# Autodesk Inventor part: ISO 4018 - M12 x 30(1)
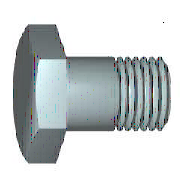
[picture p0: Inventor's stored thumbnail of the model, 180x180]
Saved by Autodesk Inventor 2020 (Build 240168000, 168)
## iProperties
Created: 2019-01
Part Number: ISO 4018 - M12 x 30(1)
Material: Ocel
Description: Šrouby se šestihrannou hlavou se závitem k hlavě. Výrobní třída C
Document SubType Name: Modeling
Standard: ISO 4018
Designer: doma
Standard Revision: Fourth edition 2011-04-01
Standards Organization: ISO
Language: cs-CZ
Size Designation: M12 x 30
Categories: <MemberInstance><Categories><Category DisplayName="Spojovací materiál" InternalName="e4da775c-781d-43d5-af7c-5136215cf5a6" Mnemonic="FSTN"><Category DisplayName
Density: 7.85 g/cm^3
Appearance: Plech
Mass: 43.0202 g
Surface Area: 21.1679 cm^2
Volume: 5.48028 cm^3
IsCustomPart: 0
Author: doma
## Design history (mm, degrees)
node "WorkPlane1"
node "WorkPoint1"
node "MSC_A1"
node "MSC_PF1"
node "MSC_PT1"
body "Solid1"
node "Náčrt1"
sketch "Náčrt2"
  geometry: L1 (-9, 5.196)-(-9, -5.196); L2 (0, 10.392)-(-9, 5.196); L3 (9, 5.196)-(0, 10.392); L4 (9, -5.196)-(9, 5.196); L5 (0, -10.392)-(9, -5.196); L6 (-9, -5.196)-(0, -10.392); C1 r 9 at (0, 0); 1 further point
  constraints: 12 end point, 6 tangent, 2 parallel, 2 vertical, 1 centre point
  dimensions: "d1" = 18 diameter of C1 (= ParS); "d29" = 0 distance of point (0, 0) C1.centre; "d30" = 0 distance of C1.centre point (0, 0)
extrude "Vysunutí1" new body sketch "Náčrt2" distance "d6" = 7.5 (= ParK); taper "d7" = 0 deg
revolve "Rotace1" stored, may be unused: angle "d14" = 360 deg
revolve "Rotace2" stored, may be unused: angle "d21" = 360 deg
chamfer "Zkosení1" distance "d22" = 0.875 (= 0.5 x PTC); stored, may be unused: second distance "d23" = 0.875 (= 0.5 x PTC), angle "d39" = 45 deg
fillet "Zaoblení1" dims "d24" = 0.6 (= r)
feature "Závit1" dims "d32" = 0, "b" = 26.5 (= NLG - 2 x PTC)
sketch "Náčrt3"
  geometry: L1 (9, 7.5)-(10.492, 7.5); L2 (10.492, 6.639)-(9, 7.5); L3 (10.492, 7.5)-(10.492, 6.639); L4 (0, -1.5)-(0, 9) reference; L5 (10.392, 0)-(10.392, 7.5) reference
  constraints: 6 end point, 1 horizontal, 1 vertical
  dimensions: "d25" = 0.1 distance between parallel lines of L5 L3; "d26" = 0 distance from line of L5.end L1; "d27" = 60 deg angle of L3 L2; "d28" = 9 distance from line of L4 L1.start (= 0.5 x ParS)
sketch "Náčrt4"
  geometry: L1 (0, -30)-(0, 0); L2 (-6, -30)-(0, -30); L3 (-6, 0)-(-6, -30); L4 (0, 0)-(-6, 0); L5 (0, -30)-(0, 0); L6 (-7.2, 0)-(1.2, 0) reference; L7 (0, -36)-(0, 6) reference
  constraints: 10 end point, 2 horizontal, 2 vertical
  dimensions: "d18" = 6 distance of L1.start L2.start (= 0.5 x NND); "d20" = 30 distance of L3.start L2.start (= NLG); "d33" = 0 distance between parallel lines of L7 L1; "d34" = 0 distance between parallel lines of L6 L4
other parameters: "NND" = 12 [user parameter; used in 2 equation terms], "NLG" = 30 [user parameter; used in 2 equation terms], "PTC" = 1.75 [user parameter; used in 3 equation terms], "ParK" = 7.5 [user parameter; used in 1 equation term], "ParS" = 18 [user parameter; used in 3 equation terms], "msp_es" = 10.39261 (= 0.577367 x ParS) [user parameter], "r" = 0.6 [user parameter; used in 1 equation term], "d2" = 15 (derived), "d4" = 17.32102 (derived), "d8" = 15 (derived), "d10" = 0 (derived), "d12" = 30 deg (derived), "d15" = 0 (derived), "d37" = 0, "d38" = 0, "d40" = 0, "d41" = 0, "d42" = 0, "THREADDIA" = 12 (= NND) [user parameter]
